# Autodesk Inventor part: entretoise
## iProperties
Created: 2011-09
Part Number: entretoise
Document SubType Name: Modeling
Designer: Dominique
Author: Dominique
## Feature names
1. Extrusion1
2. Perçage1 [Hole]
